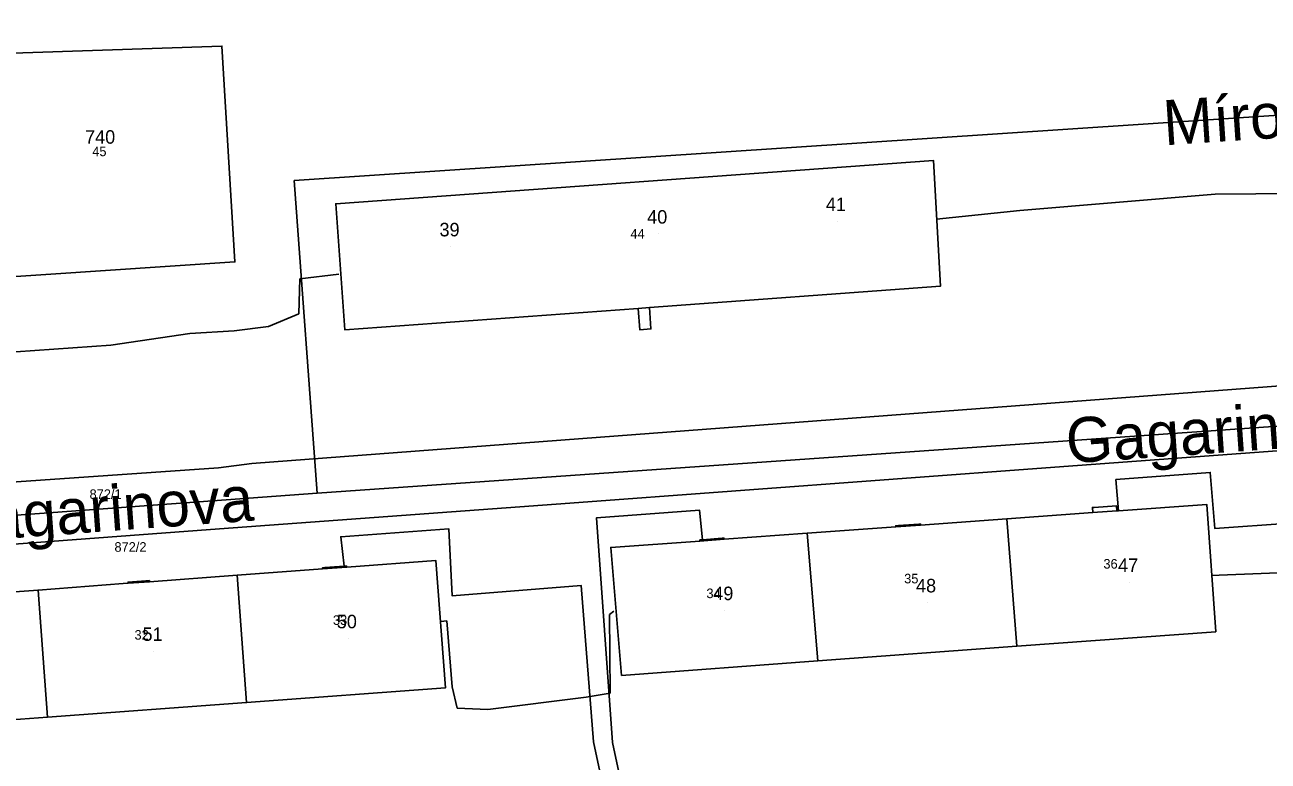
# Model space of a CAD drawing. Extents: x -873642 to -872917, y -1012962 to -1012567.
# Drawn here: x -873283.8 to -873173.4, y -1012717.8 to -1012652.4 of the extents above; entities that cross this region are included whole.
import ezdxf

# ---------------------------------------------------------------- set-up
doc = ezdxf.new("R2010")
doc.units = 0
for name, color, linetype in [('adresni_misto', 7, 'Continuous'), ('cisla_parcelni_kn', 7, 'Continuous'), ('cislo_domovni', 7, 'Continuous'), ('osy_ulic', 7, 'Continuous'), ('parcely_kn', 7, 'Continuous'), ('stavebni_objekty_bydleni', 7, 'Continuous'), ('stavebni_objekty_sluzby', 7, 'Continuous'), ('TRASY - zamereno', 7, 'Continuous'), ('ulice', 7, 'Continuous')]:
    doc.layers.add(name, color=color, linetype=linetype)

msp = doc.modelspace()

# ---------------------------------------------------------------- linework, layer by layer
at = {"layer": 'adresni_misto'}
for p, q in [((-873276.81, -1012663.9), (-873276.81, -1012663.9)), ((-873211.63, -1012669.88), (-873211.63, -1012669.88)), ((-873227.5, -1012671), (-873227.5, -1012671)), ((-873245.94, -1012672.13), (-873245.94, -1012672.13)), ((-873185.69, -1012701.94), (-873185.69, -1012701.94)), ((-873221.63, -1012704.44), (-873221.63, -1012704.44)), ((-873203.63, -1012703.75), (-873203.63, -1012703.75)), ((-873255.06, -1012706.94), (-873255.06, -1012706.94)), ((-873272.31, -1012708.06), (-873272.31, -1012708.06))]:
    msp.add_line(p, q, dxfattribs=at)
at = {"layer": 'osy_ulic'}
for points in [[(-873071.61, -1012653.78), (-873259.84, -1012666.28), (-873257.79, -1012694.05)], [(-873471.18, -1012707.47), (-873461.09, -1012708.93), (-873257.79, -1012694.05), (-873080.41, -1012681.66)]]:
    msp.add_lwpolyline(points, dxfattribs=at)
at = {"layer": 'parcely_kn'}
for points in [[(-873095.85, -1012678.72), (-873263.61, -1012691.39), (-873266.56, -1012691.78), (-873320.85, -1012695.55), (-873397.76, -1012701.2), (-873419.57, -1012702.63), (-873457.18, -1012705.12), (-873461.77, -1012705), (-873467.35, -1012700.29), (-873470.31, -1012685.53), (-873471.34, -1012679.34), (-873473.95, -1012664.84), (-873474.55, -1012659.21), (-873476.91, -1012642.49), (-873476.25, -1012638.16), (-873474.09, -1012635.88), (-873470.15, -1012634.51), (-873407.08, -1012629.93)], [(-873095.85, -1012678.72), (-873263.61, -1012691.39), (-873266.56, -1012691.78), (-873320.85, -1012695.55), (-873397.76, -1012701.2), (-873419.57, -1012702.63), (-873457.18, -1012705.12), (-873461.77, -1012705), (-873467.35, -1012700.29), (-873470.31, -1012685.53), (-873471.34, -1012679.34), (-873473.95, -1012664.84), (-873474.55, -1012659.21), (-873476.91, -1012642.49), (-873476.25, -1012638.16), (-873474.09, -1012635.88), (-873470.15, -1012634.51), (-873407.08, -1012629.93)], [(-873320.85, -1012695.55), (-873266.56, -1012691.78), (-873263.61, -1012691.39), (-873095.85, -1012678.72)], [(-873320.85, -1012695.55), (-873266.56, -1012691.78), (-873263.61, -1012691.39), (-873095.85, -1012678.72)], [(-873295.44, -1012699.37), (-873266.47, -1012697.2), (-873235.38, -1012694.94), (-873192.31, -1012691.74), (-873125.83, -1012686.85)], [(-873125.83, -1012686.85), (-873192.31, -1012691.74), (-873235.38, -1012694.94), (-873266.47, -1012697.2), (-873295.44, -1012699.37)], [(-873295.44, -1012699.37), (-873266.47, -1012697.2), (-873235.38, -1012694.94), (-873192.31, -1012691.74), (-873125.83, -1012686.85)], [(-873125.83, -1012686.85), (-873192.31, -1012691.74), (-873235.38, -1012694.94), (-873266.47, -1012697.2), (-873295.44, -1012699.37)], [(-873227.52, -1012735.13), (-873231.57, -1012716.19), (-873233.01, -1012696.23), (-873223.84, -1012695.56), (-873223.6, -1012698.17), (-873223.82, -1012698.19), (-873223.82, -1012698.29), (-873231.74, -1012698.86), (-873230.77, -1012710.22), (-873213.35, -1012708.94), (-873195.68, -1012707.64), (-873178.01, -1012706.34), (-873178.82, -1012695.03), (-873186.65, -1012695.6), (-873186.88, -1012692.83), (-873178.5, -1012692.19), (-873178.09, -1012697.19), (-873171.45, -1012696.71)], [(-873171.45, -1012696.71), (-873178.09, -1012697.19), (-873178.5, -1012692.19), (-873186.88, -1012692.83), (-873186.65, -1012695.6), (-873186.79, -1012695.61), (-873186.83, -1012695.16), (-873188.82, -1012695.3), (-873188.97, -1012695.31), (-873188.94, -1012695.76), (-873196.56, -1012696.32), (-873204.23, -1012696.87), (-873204.24, -1012696.77), (-873204.38, -1012696.78), (-873206.18, -1012696.91), (-873206.43, -1012696.93), (-873206.43, -1012697.03), (-873214.3, -1012697.6), (-873221.67, -1012698.13), (-873221.68, -1012698.03), (-873221.85, -1012698.04), (-873223.6, -1012698.17), (-873223.84, -1012695.56), (-873233.01, -1012696.23), (-873231.57, -1012716.19), (-873227.52, -1012735.13)], [(-873227.52, -1012735.13), (-873231.57, -1012716.19), (-873233.01, -1012696.23), (-873223.84, -1012695.56), (-873223.6, -1012698.17), (-873223.82, -1012698.19), (-873223.82, -1012698.29), (-873231.74, -1012698.86), (-873230.77, -1012710.22), (-873213.35, -1012708.94), (-873195.68, -1012707.64), (-873178.01, -1012706.34), (-873178.82, -1012695.03), (-873186.65, -1012695.6), (-873186.88, -1012692.83), (-873178.5, -1012692.19), (-873178.09, -1012697.19), (-873171.45, -1012696.71)], [(-873171.45, -1012696.71), (-873178.09, -1012697.19), (-873178.5, -1012692.19), (-873186.88, -1012692.83), (-873186.65, -1012695.6), (-873186.79, -1012695.61), (-873186.83, -1012695.16), (-873188.82, -1012695.3), (-873188.97, -1012695.31), (-873188.94, -1012695.76), (-873196.56, -1012696.32), (-873204.23, -1012696.87), (-873204.24, -1012696.77), (-873204.38, -1012696.78), (-873206.18, -1012696.91), (-873206.43, -1012696.93), (-873206.43, -1012697.03), (-873214.3, -1012697.6), (-873221.67, -1012698.13), (-873221.68, -1012698.03), (-873221.85, -1012698.04), (-873223.6, -1012698.17), (-873223.84, -1012695.56), (-873233.01, -1012696.23), (-873231.57, -1012716.19), (-873227.52, -1012735.13)], [(-873299.35, -1012715.23), (-873281.74, -1012713.93), (-873264.07, -1012712.63), (-873246.41, -1012711.33), (-873247.25, -1012700.02), (-873255.18, -1012700.61), (-873255.19, -1012700.51), (-873255.41, -1012700.53), (-873255.71, -1012697.91), (-873246.1, -1012697.22), (-873245.8, -1012703.16), (-873234.35, -1012702.25), (-873233.26, -1012716.13), (-873229.13, -1012735.49)], [(-873299.35, -1012715.23), (-873281.74, -1012713.93), (-873264.07, -1012712.63), (-873246.41, -1012711.33), (-873247.25, -1012700.02), (-873255.18, -1012700.61), (-873255.19, -1012700.51), (-873255.41, -1012700.53), (-873255.71, -1012697.91), (-873246.1, -1012697.22), (-873245.8, -1012703.16), (-873234.35, -1012702.25), (-873233.26, -1012716.13), (-873229.13, -1012735.49)], [(-873229.13, -1012735.49), (-873233.26, -1012716.13), (-873234.35, -1012702.25), (-873245.8, -1012703.16), (-873246.1, -1012697.22), (-873255.71, -1012697.91), (-873255.41, -1012700.53), (-873257.11, -1012700.65), (-873257.34, -1012700.67), (-873257.33, -1012700.77), (-873264.91, -1012701.33), (-873272.7, -1012701.9), (-873272.7, -1012701.8), (-873273, -1012701.82), (-873274.6, -1012701.94), (-873274.59, -1012702.04), (-873275.04, -1012702.07), (-873282.58, -1012702.64), (-873290.06, -1012703.19)], [(-873229.13, -1012735.49), (-873233.26, -1012716.13), (-873234.35, -1012702.25), (-873245.8, -1012703.16), (-873246.1, -1012697.22), (-873255.71, -1012697.91), (-873255.41, -1012700.53), (-873257.11, -1012700.65), (-873257.34, -1012700.67), (-873257.33, -1012700.77), (-873264.91, -1012701.33), (-873272.7, -1012701.9), (-873272.7, -1012701.8), (-873273, -1012701.82), (-873274.6, -1012701.94), (-873274.59, -1012702.04), (-873275.04, -1012702.07), (-873282.58, -1012702.64), (-873290.06, -1012703.19)]]:
    msp.add_lwpolyline(points, dxfattribs=at)
for points in [[(-873289.27, -1012655.1), (-873266.26, -1012654.33), (-873265.1, -1012673.5), (-873287.65, -1012675)], [(-873287.65, -1012675), (-873265.1, -1012673.5), (-873266.26, -1012654.33), (-873289.27, -1012655.1)], [(-873289.27, -1012655.1), (-873266.26, -1012654.33), (-873265.1, -1012673.5), (-873287.65, -1012675)], [(-873287.65, -1012675), (-873265.1, -1012673.5), (-873266.26, -1012654.33), (-873289.27, -1012655.1)], [(-873255.33, -1012679.54), (-873229.3, -1012677.63), (-873229.16, -1012679.52), (-873228.17, -1012679.45), (-873228.3, -1012677.56), (-873202.46, -1012675.66), (-873203.09, -1012664.48), (-873256.15, -1012668.33)], [(-873202.46, -1012675.66), (-873228.3, -1012677.56), (-873228.17, -1012679.45), (-873229.16, -1012679.52), (-873229.3, -1012677.63), (-873255.33, -1012679.54), (-873256.15, -1012668.33), (-873203.09, -1012664.48)], [(-873255.33, -1012679.54), (-873229.3, -1012677.63), (-873229.16, -1012679.52), (-873228.17, -1012679.45), (-873228.3, -1012677.56), (-873202.46, -1012675.66), (-873203.09, -1012664.48), (-873256.15, -1012668.33)], [(-873202.46, -1012675.66), (-873228.3, -1012677.56), (-873228.17, -1012679.45), (-873229.16, -1012679.52), (-873229.3, -1012677.63), (-873255.33, -1012679.54), (-873256.15, -1012668.33), (-873203.09, -1012664.48)], [(-873186.79, -1012695.61), (-873186.65, -1012695.6), (-873178.82, -1012695.03), (-873178.01, -1012706.34), (-873195.68, -1012707.64), (-873196.56, -1012696.32), (-873188.94, -1012695.76), (-873188.97, -1012695.31), (-873188.82, -1012695.3), (-873186.83, -1012695.16)], [(-873186.79, -1012695.61), (-873186.65, -1012695.6), (-873178.82, -1012695.03), (-873178.01, -1012706.34), (-873195.68, -1012707.64), (-873196.56, -1012696.32), (-873188.94, -1012695.76), (-873188.97, -1012695.31), (-873188.82, -1012695.3), (-873186.83, -1012695.16)], [(-873196.56, -1012696.32), (-873195.68, -1012707.64), (-873213.35, -1012708.94), (-873214.3, -1012697.6), (-873206.43, -1012697.03), (-873206.43, -1012696.93), (-873206.18, -1012696.91), (-873204.38, -1012696.78), (-873204.24, -1012696.77), (-873204.23, -1012696.87)], [(-873196.56, -1012696.32), (-873195.68, -1012707.64), (-873213.35, -1012708.94), (-873214.3, -1012697.6), (-873206.43, -1012697.03), (-873206.43, -1012696.93), (-873206.18, -1012696.91), (-873204.38, -1012696.78), (-873204.24, -1012696.77), (-873204.23, -1012696.87)], [(-873214.3, -1012697.6), (-873213.35, -1012708.94), (-873230.77, -1012710.22), (-873231.74, -1012698.86), (-873223.82, -1012698.29), (-873223.82, -1012698.19), (-873223.6, -1012698.17), (-873221.85, -1012698.04), (-873221.68, -1012698.03), (-873221.67, -1012698.13)], [(-873214.3, -1012697.6), (-873213.35, -1012708.94), (-873230.77, -1012710.22), (-873231.74, -1012698.86), (-873223.82, -1012698.29), (-873223.82, -1012698.19), (-873223.6, -1012698.17), (-873221.85, -1012698.04), (-873221.68, -1012698.03), (-873221.67, -1012698.13)], [(-873247.25, -1012700.02), (-873246.41, -1012711.33), (-873264.07, -1012712.63), (-873264.91, -1012701.33), (-873257.33, -1012700.77), (-873257.34, -1012700.67), (-873257.11, -1012700.65), (-873255.41, -1012700.53), (-873255.19, -1012700.51), (-873255.18, -1012700.61)], [(-873247.25, -1012700.02), (-873246.41, -1012711.33), (-873264.07, -1012712.63), (-873264.91, -1012701.33), (-873257.33, -1012700.77), (-873257.34, -1012700.67), (-873257.11, -1012700.65), (-873255.41, -1012700.53), (-873255.19, -1012700.51), (-873255.18, -1012700.61)], [(-873264.91, -1012701.33), (-873264.07, -1012712.63), (-873281.74, -1012713.93), (-873282.58, -1012702.64), (-873275.04, -1012702.07), (-873274.59, -1012702.04), (-873274.6, -1012701.94), (-873273, -1012701.82), (-873272.7, -1012701.8), (-873272.7, -1012701.9)], [(-873264.91, -1012701.33), (-873264.07, -1012712.63), (-873281.74, -1012713.93), (-873282.58, -1012702.64), (-873275.04, -1012702.07), (-873274.59, -1012702.04), (-873274.6, -1012701.94), (-873273, -1012701.82), (-873272.7, -1012701.8), (-873272.7, -1012701.9)], [(-873282.58, -1012702.64), (-873281.74, -1012713.93), (-873299.35, -1012715.23), (-873300.19, -1012703.94), (-873292.31, -1012703.36), (-873292.31, -1012703.26), (-873291.89, -1012703.23), (-873290.19, -1012703.11), (-873290.07, -1012703.09), (-873290.06, -1012703.19)], [(-873282.58, -1012702.64), (-873281.74, -1012713.93), (-873299.35, -1012715.23), (-873300.19, -1012703.94), (-873292.31, -1012703.36), (-873292.31, -1012703.26), (-873291.89, -1012703.23), (-873290.19, -1012703.11), (-873290.07, -1012703.09), (-873290.06, -1012703.19)]]:
    msp.add_lwpolyline(points, close=True, dxfattribs=at)
at = {"layer": 'stavebni_objekty_bydleni'}
for points in [[(-873228.3, -1012677.56), (-873229.3, -1012677.63), (-873255.33, -1012679.54), (-873256.15, -1012668.33), (-873203.09, -1012664.48), (-873202.46, -1012675.66)], [(-873186.65, -1012695.6), (-873178.82, -1012695.03), (-873178.01, -1012706.34), (-873195.68, -1012707.64), (-873213.35, -1012708.94), (-873230.77, -1012710.22), (-873231.74, -1012698.86), (-873223.82, -1012698.29), (-873221.67, -1012698.13), (-873214.3, -1012697.6), (-873206.43, -1012697.03), (-873204.23, -1012696.87), (-873196.56, -1012696.32), (-873188.94, -1012695.76), (-873186.79, -1012695.61)], [(-873274.59, -1012702.04), (-873272.7, -1012701.9), (-873264.91, -1012701.33), (-873257.33, -1012700.77), (-873255.18, -1012700.61), (-873247.25, -1012700.02), (-873246.41, -1012711.33), (-873264.07, -1012712.63), (-873281.74, -1012713.93), (-873299.35, -1012715.23), (-873300.19, -1012703.94), (-873292.31, -1012703.36), (-873290.06, -1012703.19), (-873282.58, -1012702.64), (-873275.04, -1012702.07)]]:
    msp.add_lwpolyline(points, close=True, dxfattribs=at)
at = {"layer": 'stavebni_objekty_sluzby'}
msp.add_lwpolyline([(-873289.27, -1012655.1), (-873266.26, -1012654.33), (-873265.1, -1012673.5), (-873287.65, -1012675)], close=True, dxfattribs=at)
at = {"layer": 'TRASY - zamereno'}
for p, q in [((-873178.06, -1012667.48), (-873195.4, -1012668.94)), ((-873169.01, -1012667.4), (-873178.06, -1012667.48)), ((-873195.4, -1012668.94), (-873202.8, -1012669.7)), ((-873255.88, -1012674.6), (-873259.33, -1012675)), ((-873259.33, -1012675), (-873259.44, -1012678.1)), ((-873259.44, -1012678.1), (-873262.11, -1012679.24)), ((-873262.11, -1012679.24), (-873265.18, -1012679.61)), ((-873269.1, -1012679.86), (-873276.11, -1012680.9)), ((-873265.18, -1012679.61), (-873269.1, -1012679.86)), ((-873276.11, -1012680.9), (-873289.6, -1012681.83)), ((-873177.71, -1012701.33), (-873178.4, -1012701.36)), ((-873171, -1012701.05), (-873177.71, -1012701.33)), ((-873231.45, -1012704.51), (-873231.83, -1012704.8)), ((-873246.3, -1012705.37), (-873246.82, -1012705.45)), ((-873245.82, -1012711.25), (-873246.3, -1012705.37)), ((-873231.83, -1012704.8), (-873231.8, -1012711.8)), ((-873245.37, -1012713.12), (-873245.82, -1012711.25)), ((-873233.91, -1012712.16), (-873242.64, -1012713.25)), ((-873231.8, -1012711.8), (-873233.91, -1012712.16)), ((-873242.64, -1012713.25), (-873245.37, -1012713.12))]:
    msp.add_line(p, q, dxfattribs=at)

# ---------------------------------------------------------------- texts
at = {"layer": 'cisla_parcelni_kn'}
for s, p in [('45', (-873277.77, -1012664.11)), ('45', (-873277.77, -1012664.11)), ('44', (-873229.99, -1012671.43)), ('44', (-873229.99, -1012671.43)), ('872/1', (-873278.01, -1012694.55)), ('872/1', (-873278.01, -1012694.55)), ('872/2', (-873275.8, -1012699.24)), ('872/2', (-873275.8, -1012699.24)), ('36', (-873187.99, -1012700.74)), ('36', (-873187.99, -1012700.74)), ('35', (-873205.68, -1012702.05)), ('35', (-873205.68, -1012702.05)), ('34', (-873223.24, -1012703.36)), ('34', (-873223.24, -1012703.36)), ('33', (-873256.4, -1012705.74)), ('33', (-873256.4, -1012705.74)), ('32', (-873274.02, -1012707.05)), ('32', (-873274.02, -1012707.05))]:
    msp.add_text(s, height=0.85, dxfattribs=at).set_placement(p)
at = {"layer": 'cislo_domovni'}
for s, p in [('740', (-873278.41, -1012663)), ('41', (-873212.63, -1012668.98)), ('40', (-873228.5, -1012670.1)), ('39', (-873246.94, -1012671.23)), ('47', (-873186.69, -1012701.04)), ('49', (-873222.63, -1012703.54)), ('48', (-873204.63, -1012702.85)), ('50', (-873256.06, -1012706.04)), ('51', (-873273.31, -1012707.16))]:
    msp.add_text(s, height=1.2, dxfattribs=at).set_placement(p)
at = {"layer": 'ulice'}
for s, rotation, p in [('Mírová', 3.7993, (-873182.57, -1012663.15)), ('Gagarinova', 3.9956, (-873191.18, -1012691.4)), ('Gagarinova', 4.1861, (-873290.93, -1012698.48))]:
    msp.add_text(s, height=4, rotation=rotation, dxfattribs=at).set_placement(p)

doc.saveas('drawing.dxf')
